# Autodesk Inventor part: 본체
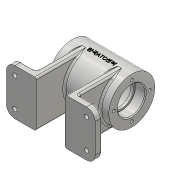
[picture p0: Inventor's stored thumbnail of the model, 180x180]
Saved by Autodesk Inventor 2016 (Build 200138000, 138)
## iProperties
Created: 2017-02
Part Number: 본체
Material: 알루미늄 6061
Document SubType Name: Modeling
Designer: H
Density: 2.7 g/cm^3
Appearance: 알루미늄 - 평지
Mass: 354.509 g
Surface Area: 423.333 cm^2
Volume: 131.3 cm^3
Author: H
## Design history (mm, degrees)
sketch "스케치1"
  geometry: L1 (0, 0)-(48.276, 0); L2 (0, 0)-(-37.135, 0); L3 (-35, 0)-(-35, 27); L4 (-35, 27)-(35, 27); L5 (35, 27)-(35, 0); L6 (0, 0)-(0, 35.697)
  constraints: 12 end point, 2 horizontal, 2 perpendicular, 2 point on line, 2 vertical
  dimensions: "d0" = 70 distance of L3.end L4.end; "d1" = 70 diameter of L3 L6; "d2" = 54 diameter of L4 L1
revolve "회전1" sketch "스케치1" stored, may be unused: angle "d3" = 90 deg
node "작업 평면1"
sketch "스케치2"
  geometry: L1 (35, 27)-(35, -27) reference; L2 (-35, 27)-(-35, -27) reference; L3 (0, 0)-(-50.692, 0); L4 (0, 0)-(76.762, 0); L5 (52, 27)-(-52, 27); L6 (-52, 27)-(-52, -27); L7 (-52, -27)-(52, -27); L8 (52, -27)-(52, 27); L9 (52, 27)-(-52, -27); L10 (-52, 27)-(52, -27)
  constraints: 16 end point, 3 horizontal, 2 midpoint, 2 parallel, 1 perpendicular
  dimensions: "d5" = 54 distance of L5.end L6.end; "d6" = 104 distance of L5.start L5.end
extrude "돌출1" join sketch "스케치2" distance "d7" = 8; taper "d8" = 0 deg
sketch "스케치3"
  geometry: L1 (0, 0)-(104, 0) reference; L2 (104, 0)-(104, 8) reference; L3 (0, 8)-(104, 8) reference; L4 (0, 0)-(0, 8) reference; L5 (52, 8)-(52, 0); L6 (69, 8)-(69, 0); L7 (35, 8)-(35, 0); L8 (35, 0)-(69, 0); L9 (35, 8)-(69, 8); 1 further point
  constraints: 10 end point, 2 midpoint, 2 perpendicular, 2 point on line, 2 symmetric about line, 1 collinear
  dimensions: "d9" = 17 distance from line of L6 L5.start
extrude "돌출2" cut sketch "스케치3" stored distance "d10" = 8; taper "d11" = 0 deg
sketch "스케치4"
  geometry: L1 (17, -27)-(17, 27) reference; L2 (52, 27)-(17, 27) reference; L3 (52, -27)-(52, 27) reference; L4 (17, -27)-(52, -27) reference; L5 (-17, 27)-(-17, -27) reference; L6 (-52, -27)-(-17, -27) reference; L7 (-52, 27)-(-52, -27) reference; L8 (-17, 27)-(-52, 27) reference; L9 (25, 27)-(25, -27); L10 (-25, 27)-(-25, -27); L11 (-25, 27)-(-17, 27); L12 (-17, 27)-(-17, -27); L13 (-17, -27)-(-25, -27); L14 (17, -27)-(25, -27); L15 (17, -27)-(17, 27); L16 (17, 27)-(25, 27); 1 further point
  constraints: 16 end point, 5 collinear, 4 point on line, 2 perpendicular, 1 vertical
  dimensions: "d12" = 8 distance between parallel lines of L9 L1; "d13" = 8 distance between parallel lines of L5 L10
extrude "돌출3" join sketch "스케치4" stored distance "d14" = 0; taper "d15" = 0 deg
fillet "모깎기1" dims "d16" = 10, "d17" = 10, "d18" = 10, "d19" = 10
sketch "스케치5"
  geometry: L1 (17, -27)-(42, -27) reference; L2 (17, -27)-(17, 27) reference; L3 (42, 27)-(17, 27) reference; L4 (52, -17)-(52, 17) reference; L5 (-17, 27)-(-42, 27) reference; L6 (-17, 27)-(-17, -27) reference; L7 (-42, -27)-(-17, -27) reference; L8 (-52, 17)-(-52, -17) reference; L9 (44.598, 21.5)-(47.196, 17); L10 (47.196, 17)-(44.598, 12.5); L11 (44.598, 12.5)-(39.402, 12.5); L12 (39.402, 12.5)-(36.804, 17); L13 (36.804, 17)-(39.402, 21.5); L14 (39.402, 21.5)-(44.598, 21.5); L15 (0, 0)-(12.572, 0); L16 (0, 0)-(0, 12.516); L17 (47.196, -17)-(44.598, -12.5); L18 (39.402, -12.5)-(36.804, -17); L19 (44.598, -21.5)-(47.196, -17); L20 (39.402, -21.5)-(44.598, -21.5); L21 (36.804, -17)-(39.402, -21.5); L22 (44.598, -12.5)-(39.402, -12.5); L23 (-44.598, -12.5)-(-39.402, -12.5); L24 (-39.402, -12.5)-(-36.804, -17); L25 (-47.196, -17)-(-44.598, -12.5); L26 (-36.804, -17)-(-39.402, -21.5); L27 (-39.402, -21.5)-(-44.598, -21.5); L28 (-44.598, -21.5)-(-47.196, -17); L29 (-36.804, 17)-(-39.402, 21.5); L30 (-39.402, 21.5)-(-44.598, 21.5); L31 (-44.598, 12.5)-(-39.402, 12.5); L32 (-44.598, 21.5)-(-47.196, 17); L33 (-47.196, 17)-(-44.598, 12.5); L34 (-39.402, 12.5)-(-36.804, 17); A1 r 10 centre (42, -17) between (42, -27) and (52, -17) reference; A2 r 10 centre (42, 17) between (52, 17) and (42, 27) reference; A3 r 10 centre (-42, 17) between (-42, 27) and (-52, 17) reference; A4 r 10 centre (-42, -17) between (-52, -17) and (-42, -27) reference; A5 r 10 centre (-42, 17) between (-42, 27) and (-52, 17); 11 further points
  constraints: 52 end point, 28 symmetric about line, 2 point on circle, 1 centre point, 1 horizontal, 1 midpoint, 1 vertical, 14 other
extrude "돌출4" cut sketch "스케치5" distance "d21" = 3; taper "d22" = 0 deg
sketch "스케치6"
  geometry: L1 (17, -27)-(42, -27) reference; L2 (17, -27)-(17, 27) reference; L3 (42, 27)-(17, 27) reference; L4 (52, -17)-(52, 17) reference; L5 (-17, 27)-(-42, 27) reference; L6 (-17, 27)-(-17, -27) reference; L7 (-42, -27)-(-17, -27) reference; L8 (-52, 17)-(-52, -17) reference; A1 r 10 centre (42, -17) between (42, -27) and (52, -17) reference; A2 r 10 centre (42, 17) between (52, 17) and (42, 27) reference; A3 r 10 centre (-42, 17) between (-42, 27) and (-52, 17) reference; A4 r 10 centre (-42, -17) between (-52, -17) and (-42, -27) reference; 5 further points
  constraints: 4 coincident
hole "구멍1" sketch "스케치6" at (-42, -17), (-42, 17), (42, 17), (42, -17) diameter "d23" = 5; stored, may be unused: countersink angle "d27" = 90 deg, drill point angle "d29" = 0 deg; dims "d24" = 6, "d25" = 4, "d26" = 2, "d28" = 8
sketch "스케치7"
  geometry: L1 (-35, -27)-(-35, 27) reference; L2 (-35, 27)-(35, 27) reference; L3 (35, -27)-(35, 27) reference; L4 (-35, -27)-(35, -27) reference; L5 (0, 0)-(22.79, 0); L6 (-35, 16)-(-23, 16); L7 (-23, 16)-(-23, 14); L8 (-23, 14)-(-20, 14); L9 (-20, 14)-(-20, 22); L10 (-20, 22)-(20, 22); L11 (20, 22)-(20, 14); L12 (20, 14)-(23, 14); L13 (23, 14)-(23, 16); L14 (23, 16)-(35, 16); L15 (-35, 16)-(-35, 0); L16 (35, 16)-(35, 0); L17 (-35, 0)-(35, 0)
  constraints: 26 end point, 7 perpendicular, 6 point on line, 2 horizontal, 2 midpoint
  dimensions: "d30" = 32 diameter of L14 L5; "d31" = 44 diameter of L10 L5; "d32" = 28 diameter of L12 L5; "d33" = 12 distance between parallel lines of L1 L7; "d34" = 40 distance between parallel lines of L11 L9; "d35" = 12 distance between parallel lines of L3 L13; "d36" = 3 distance of L11.end L12.end
revolve "회전2" sketch "스케치7" stored, may be unused: angle "d37" = 90 deg
sketch "스케치8"
  geometry: L1 (-35, 27)-(35, 27) reference; L2 (-35, -27)-(-35, 27) reference; L3 (-10, 27)-(-10, 42.717); L4 (-15, 27)-(-15, 32); L5 (-15, 32)-(-10, 32); L6 (-15, 27)-(-10, 27); 1 further point
  constraints: 8 end point, 3 point on line, 2 vertical, 1 collinear, 1 perpendicular
  dimensions: "d38" = 5 distance between parallel lines of L1 L5; "d39" = 25 distance from line of L2 L3.end; "d40" = 10 diameter of L4 L3
revolve "회전3" sketch "스케치8" stored, may be unused: angle "d41" = 90 deg
sketch "스케치9"
  geometry: C1 r 5 at (0, 0) reference; C2 r 5 at (0, 0); 1 further point
  constraints: 1 centre point, 1 coincident, 1 concentric
extrude "돌출5" join sketch "스케치9" stored distance "d42" = 3; taper "d43" = 0 deg
sketch "스케치10"
  geometry: L1 (0, 0)-(-32.149, 0); L2 (0, 0)-(-25.16, -16.339); C1 r 16 at (0, 0) reference; C2 r 27 at (0, 0) reference; 1 further point
  constraints: 4 end point, 1 horizontal
  dimensions: "d44" = 33 deg angle of L2 L1; "d45" = 30 distance of L1.start L2.end
  node "투영된 루프10"
node "작업 평면2"
sketch "스케치11"
  geometry: C1 r 6 at (0, 0); 1 further point
  constraints: 1 centre point, 1 coincident
  dimensions: "d46" = 12 diameter of C1
extrude "돌출6" join sketch "스케치11" stored distance "d47" = 0; taper "d48" = 0 deg
node "작업 평면3"
sketch "스케치12"
  geometry: L1 (-35, -27)-(-35, 27) reference; L2 (-35, 27)-(35, 27) reference; 2 further points
  constraints: 1 other
  dimensions: "d50" = 35 distance from line of point (0, 0) L1; "d51" = 27 distance from line of L2 point (0, 0)
feature "엠보싱1" sketch "스케치12" dims "d0" = 70, "d1" = 70, "d2" = 54, "d52" = 0.5, "d53" = 0
sketch "스케치13"
  geometry: C1 r 5 at (0, 0) reference; 2 further points
  constraints: 1 coincident
hole "구멍2" sketch "스케치13" at (0, 0) diameter "d54" = 5.188; stored, may be unused: countersink angle "d58" = 90 deg, drill point angle "d60" = 0 deg; dims "d55" = 30, "d56" = 4, "d57" = 2, "d59" = 16
sketch "스케치14"
  geometry: C1 r 6 at (0, 0) reference; 2 further points
  constraints: 1 coincident
hole "구멍3" sketch "스케치14" at (0, 0) diameter "d61" = 5.188; stored, may be unused: countersink angle "d65" = 90 deg, drill point angle "d67" = 0 deg; dims "d62" = 15, "d63" = 4, "d64" = 2, "d66" = 20
fillet "모깎기2" dims "d68" = 2
fillet "모깎기3" dims "d69" = 2
fillet "모깎기4" dims "d70" = 3
fillet "모깎기5" dims "d71" = 2
fillet "모깎기6" dims "d72" = 2
fillet "모깎기7" dims "d73" = 2
fillet "모깎기8" dims "d74" = 2
chamfer "모따기1" distance "d75" = 1; stored, may be unused: second distance "d76" = 2, angle "d77" = 45 deg
chamfer "모따기2" distance "d78" = 1; stored, may be unused: second distance "d79" = 2, angle "d80" = 45 deg
sketch "스케치15" dims "d81" = 42
  geometry: C1 r 27 at (0, 0) reference; C2 r 17 at (0, 0) reference; 3 further points
  constraints: 1 coincident, 1 vertical alignment, 2 other
hole "구멍4" sketch "스케치15" at (0, 21) diameter "d82" = 3.459; stored, may be unused: countersink angle "d86" = 90 deg, drill point angle "d88" = 118 deg; dims "d83" = 8, "d84" = 4, "d85" = 2, "d87" = 10
fillet "모깎기9" dims "d92" = 0.3, "d93" = 0.3
node "솔리드1"
pattern_circular "원형 패턴1" dims angle "d90" = 360 deg
mirror "대칭1"
node "투영된 루프1"
node "투영된 루프2"
node "투영된 루프3"
node "투영된 루프4"
node "투영된 루프5"
node "투영된 루프6"
node "투영된 루프7"
node "투영된 루프8"
node "투영된 루프9"
node "투영된 루프11"
node "투영된 루프12"
node "투영된 루프13"
other parameters: "d49" = 70.5
